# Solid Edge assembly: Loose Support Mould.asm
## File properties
Author: davee
Template: Normal.asm
Last saved by: davee
Revision: 72
Application: Solid Edge
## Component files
MH Corepin 1.par
Top Core Plate.par
Bottom Core Plate.par
MH Die Plate.par
FH Die Plate.par
Ejector Plate Top.par
FH Clamping Plate.par
MH Die Plate Outer.par
Support Plate.par
Riser.par
Ejector Plate Bottom.par
MH Insert3.par
MH Clamping Plate.par
Heel Block.par
Cylinder Mounting Plate.par
Air Cylinder dnc50.par
MH Corepin 2.par
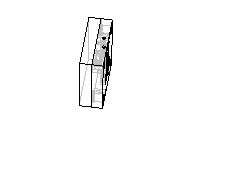
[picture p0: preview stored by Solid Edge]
